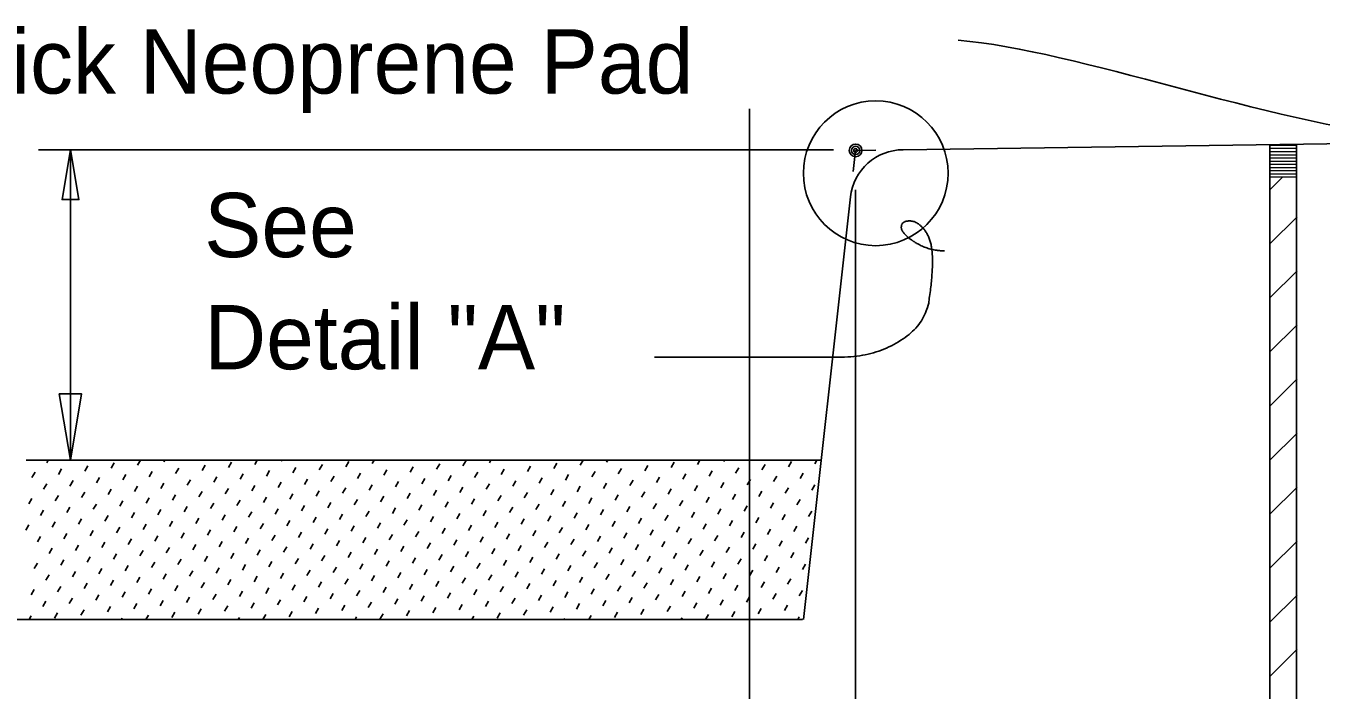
# Model space of a CAD drawing. Extents: x 21629.5 to 21698.8, y 56199.4 to 56237.6.
# Drawn here: x 21656.357 to 21660.425, y 56226.147 to 56228.232 of the extents above; entities that cross this region are included whole.
import ezdxf

# ---------------------------------------------------------------- set-up
doc = ezdxf.new("R2010")
doc.units = 0
for name, color, linetype in [('Dimension', 7, 'Continuous'), ('ExistSuperStruct', 7, 'Continuous'), ('Miscellaneous', 7, 'Continuous'), ('TextStructures', 7, 'Continuous')]:
    doc.layers.add(name, color=color, linetype=linetype)

msp = doc.modelspace()

# ---------------------------------------------------------------- linework, layer by layer
at = {"layer": 'Dimension'}
for p, q in [((21658.6296, 56224.0819), (21658.6296, 56227.9716)), ((21658.8938, 56227.8432), (21656.3966, 56227.8432)), ((21656.4966, 56227.8432), (21656.4966, 56226.8686)), ((21658.9631, 56227.8412), (21658.9557, 56227.7748)), ((21658.9631, 56227.8412), (21659.0262, 56227.8421)), ((21658.963, 56223.3626), (21658.963, 56227.7178))]:
    msp.add_line(p, q, dxfattribs=at)
for points in [[(21656.4967, 56227.8432), (21656.4703, 56227.687), (21656.5232, 56227.687)], [(21656.4966, 56226.8686), (21656.5319, 56227.0768), (21656.4614, 56227.0768)]]:
    msp.add_lwpolyline(points, close=True, dxfattribs=at)
for centre, radius in [((21659.0261, 56227.7695), 0.2273), ((21658.9631, 56227.8412), 0.0199), ((21658.9631, 56227.8412), 0.0131), ((21658.9631, 56227.8412), 0.00592)]:
    msp.add_circle(centre, radius, dxfattribs=at)
for points, degree in [([(21659.2853, 56228.1872), (21659.6642, 56228.1541), (21660.2494, 56227.9294), (21660.7118, 56227.8802)], 3), ([(21658.3309, 56227.1921), (21658.8009, 56227.1921), (21659.0206, 56227.1921), (21659.1804, 56227.2921), (21659.2044, 56227.436), (21659.2044, 56227.5579), (21659.1584, 56227.6199), (21659.1065, 56227.6199), (21659.1065, 56227.5799), (21659.1924, 56227.5259), (21659.2423, 56227.5259)], 2)]:
    msp.add_open_spline(points, degree=degree, dxfattribs=at)
at = {"layer": 'ExistSuperStruct'}
for p, q in [((21659.1125, 56227.8432), (21662.7249, 56227.8927)), ((21660.2645, 56225.0569), (21660.2645, 56227.8585)), ((21660.3479, 56224.8118), (21660.3479, 56227.8597)), ((21658.9468, 56227.695), (21658.7995, 56226.3686)), ((21658.7963, 56226.3686), (21654.863, 56226.3686))]:
    msp.add_line(p, q, dxfattribs=at)
msp.add_arc((21659.1125, 56227.6766), 0.1667, 90, 173.6598, dxfattribs=at)
at = {"layer": 'Miscellaneous'}
for p, q in [((21660.2647, 56227.8567), (21660.3481, 56227.8578)), ((21660.2648, 56227.8467), (21660.3482, 56227.8478)), ((21660.2649, 56227.8367), (21660.3483, 56227.8378)), ((21660.2651, 56227.8267), (21660.3485, 56227.8278)), ((21660.2652, 56227.8167), (21660.3486, 56227.8178)), ((21660.2653, 56227.8067), (21660.3487, 56227.8078)), ((21660.2655, 56227.7967), (21660.3489, 56227.7978)), ((21660.2656, 56227.7867), (21660.349, 56227.7878)), ((21660.2657, 56227.7767), (21660.3491, 56227.7778)), ((21660.2659, 56227.7667), (21660.3493, 56227.7678)), ((21660.2645, 56227.7177), (21660.3047, 56227.7578)), ((21660.266, 56227.7567), (21660.3494, 56227.7578)), ((21660.2645, 56227.548), (21660.3494, 56227.6329)), ((21660.2645, 56227.3783), (21660.3494, 56227.4632)), ((21660.2645, 56227.2085), (21660.3494, 56227.2935)), ((21660.2645, 56227.0388), (21660.3494, 56227.1237)), ((21660.2645, 56226.8691), (21660.3494, 56226.954)), ((21658.855, 56226.8686), (21656.3573, 56226.8686)), ((21656.3758, 56226.8147), (21656.3855, 56226.8314)), ((21656.4221, 56226.861), (21656.4265, 56226.8686)), ((21656.4587, 56226.8244), (21656.4685, 56226.8412)), ((21656.5417, 56226.8341), (21656.5514, 56226.8509)), ((21656.6246, 56226.8438), (21656.6343, 56226.8606)), ((21656.7075, 56226.8535), (21656.7163, 56226.8686)), ((21656.7442, 56226.8169), (21656.7539, 56226.8337)), ((21656.7905, 56226.8633), (21656.7936, 56226.8686)), ((21656.8271, 56226.8267), (21656.8368, 56226.8435)), ((21656.91, 56226.8364), (21656.9197, 56226.8532)), ((21656.993, 56226.8461), (21657.0027, 56226.8629)), ((21657.0759, 56226.8558), (21657.0833, 56226.8686)), ((21657.1125, 56226.8192), (21657.1222, 56226.836)), ((21657.1588, 56226.8655), (21657.1606, 56226.8686)), ((21657.1954, 56226.8289), (21657.2052, 56226.8457)), ((21657.2784, 56226.8387), (21657.2881, 56226.8555)), ((21657.3613, 56226.8484), (21657.371, 56226.8652)), ((21657.4443, 56226.8581), (21657.4503, 56226.8686)), ((21657.4809, 56226.8215), (21657.4906, 56226.8383)), ((21657.5272, 56226.8678), (21657.5276, 56226.8686)), ((21657.5638, 56226.8312), (21657.5735, 56226.848)), ((21657.6467, 56226.8409), (21657.6565, 56226.8577)), ((21657.7297, 56226.8507), (21657.7394, 56226.8675)), ((21657.7663, 56226.8141), (21657.776, 56226.8309)), ((21657.8126, 56226.8604), (21657.8174, 56226.8686)), ((21657.8492, 56226.8238), (21657.8589, 56226.8406)), ((21657.9322, 56226.8335), (21657.9419, 56226.8503)), ((21658.0151, 56226.8432), (21658.0248, 56226.86)), ((21658.098, 56226.853), (21658.1071, 56226.8686)), ((21658.1346, 56226.8163), (21658.1444, 56226.8331)), ((21658.181, 56226.8627), (21658.1844, 56226.8686)), ((21658.2176, 56226.8261), (21658.2273, 56226.8429)), ((21658.3005, 56226.8358), (21658.3102, 56226.8526)), ((21658.3835, 56226.8455), (21658.3932, 56226.8623)), ((21658.4664, 56226.8552), (21658.4741, 56226.8686)), ((21658.503, 56226.8186), (21658.5127, 56226.8354)), ((21658.5493, 56226.865), (21658.5514, 56226.8686)), ((21658.5859, 56226.8284), (21658.5957, 56226.8451)), ((21658.6689, 56226.8381), (21658.6786, 56226.8549)), ((21658.7518, 56226.8478), (21658.7615, 56226.8646)), ((21658.8348, 56226.8575), (21658.8412, 56226.8686)), ((21656.4124, 56226.778), (21656.4221, 56226.7948)), ((21656.4953, 56226.7878), (21656.5051, 56226.8046)), ((21656.5783, 56226.7975), (21656.588, 56226.8143)), ((21656.6612, 56226.8072), (21656.6709, 56226.824)), ((21656.7808, 56226.7803), (21656.7905, 56226.7971)), ((21656.8637, 56226.7901), (21656.8734, 56226.8068)), ((21656.9466, 56226.7998), (21656.9564, 56226.8166)), ((21657.0296, 56226.8095), (21657.0393, 56226.8263)), ((21657.1491, 56226.7826), (21657.1588, 56226.7994)), ((21657.2321, 56226.7923), (21657.2418, 56226.8091)), ((21657.315, 56226.8021), (21657.3247, 56226.8189)), ((21657.3979, 56226.8118), (21657.4077, 56226.8286)), ((21657.4345, 56226.7752), (21657.4443, 56226.792)), ((21657.5175, 56226.7849), (21657.5272, 56226.8017)), ((21657.6004, 56226.7946), (21657.6101, 56226.8114)), ((21657.6834, 56226.8043), (21657.6931, 56226.8211)), ((21657.8029, 56226.7775), (21657.8126, 56226.7942)), ((21657.8858, 56226.7872), (21657.8956, 56226.804)), ((21657.9688, 56226.7969), (21657.9785, 56226.8137)), ((21658.0517, 56226.8066), (21658.0614, 56226.8234)), ((21658.1713, 56226.7797), (21658.181, 56226.7965)), ((21658.2542, 56226.7895), (21658.2639, 56226.8063)), ((21658.3371, 56226.7992), (21658.3469, 56226.816)), ((21658.4201, 56226.8089), (21658.4298, 56226.8257)), ((21658.5396, 56226.782), (21658.5493, 56226.7988)), ((21658.6226, 56226.7917), (21658.6323, 56226.8085)), ((21658.7055, 56226.8015), (21658.7152, 56226.8183)), ((21658.7884, 56226.8112), (21658.7981, 56226.828)), ((21658.825, 56226.7746), (21658.8348, 56226.7914)), ((21656.449, 56226.7414), (21656.4587, 56226.7582)), ((21656.5319, 56226.7512), (21656.5417, 56226.768)), ((21656.6149, 56226.7609), (21656.6246, 56226.7777)), ((21656.6978, 56226.7706), (21656.7075, 56226.7874)), ((21656.7344, 56226.734), (21656.7442, 56226.7508)), ((21656.8174, 56226.7437), (21656.8271, 56226.7605)), ((21656.9003, 56226.7534), (21656.91, 56226.7702)), ((21656.9832, 56226.7632), (21656.993, 56226.78)), ((21657.0662, 56226.7729), (21657.0759, 56226.7897)), ((21657.1028, 56226.7363), (21657.1125, 56226.7531)), ((21657.1857, 56226.746), (21657.1954, 56226.7628)), ((21657.2687, 56226.7557), (21657.2784, 56226.7725)), ((21657.3516, 56226.7654), (21657.3613, 56226.7822)), ((21657.4711, 56226.7386), (21657.4809, 56226.7554)), ((21657.5541, 56226.7483), (21657.5638, 56226.7651)), ((21657.637, 56226.758), (21657.6467, 56226.7748)), ((21657.72, 56226.7677), (21657.7297, 56226.7845)), ((21657.8395, 56226.7408), (21657.8492, 56226.7576)), ((21657.9224, 56226.7506), (21657.9322, 56226.7674)), ((21658.0054, 56226.7603), (21658.0151, 56226.7771)), ((21658.0883, 56226.77), (21658.098, 56226.7868)), ((21658.1249, 56226.7334), (21658.1346, 56226.7502)), ((21658.2079, 56226.7431), (21658.2176, 56226.7599)), ((21658.2908, 56226.7529), (21658.3005, 56226.7696)), ((21658.3737, 56226.7626), (21658.3835, 56226.7794)), ((21658.4567, 56226.7723), (21658.4664, 56226.7891)), ((21658.4933, 56226.7357), (21658.503, 56226.7525)), ((21658.5762, 56226.7454), (21658.5859, 56226.7622)), ((21658.6592, 56226.7551), (21658.6689, 56226.7719)), ((21658.7421, 56226.7649), (21658.7518, 56226.7817)), ((21660.2645, 56226.6994), (21660.3494, 56226.7843)), ((21656.3661, 56226.7317), (21656.3758, 56226.7485)), ((21656.4027, 56226.6951), (21656.4124, 56226.7119)), ((21656.4856, 56226.7048), (21656.4953, 56226.7216)), ((21656.5686, 56226.7146), (21656.5783, 56226.7313)), ((21656.6515, 56226.7243), (21656.6612, 56226.7411)), ((21656.771, 56226.6974), (21656.7808, 56226.7142)), ((21656.854, 56226.7071), (21656.8637, 56226.7239)), ((21656.9369, 56226.7168), (21656.9466, 56226.7336)), ((21657.0198, 56226.7266), (21657.0296, 56226.7434)), ((21657.1394, 56226.6997), (21657.1491, 56226.7165)), ((21657.2223, 56226.7094), (21657.2321, 56226.7262)), ((21657.3053, 56226.7191), (21657.315, 56226.7359)), ((21657.3882, 56226.7288), (21657.3979, 56226.7456)), ((21657.4248, 56226.6922), (21657.4345, 56226.709)), ((21657.5078, 56226.702), (21657.5175, 56226.7188)), ((21657.5907, 56226.7117), (21657.6004, 56226.7285)), ((21657.6736, 56226.7214), (21657.6834, 56226.7382)), ((21657.7566, 56226.7311), (21657.7663, 56226.7479)), ((21657.7932, 56226.6945), (21657.8029, 56226.7113)), ((21657.8761, 56226.7042), (21657.8858, 56226.721)), ((21657.959, 56226.714), (21657.9688, 56226.7308)), ((21658.042, 56226.7237), (21658.0517, 56226.7405)), ((21658.1615, 56226.6968), (21658.1713, 56226.7136)), ((21658.2445, 56226.7065), (21658.2542, 56226.7233)), ((21658.3274, 56226.7162), (21658.3371, 56226.733)), ((21658.4103, 56226.726), (21658.4201, 56226.7428)), ((21658.5299, 56226.6991), (21658.5396, 56226.7159)), ((21658.6128, 56226.7088), (21658.6226, 56226.7256)), ((21658.6958, 56226.7185), (21658.7055, 56226.7353)), ((21658.7787, 56226.7283), (21658.7884, 56226.745)), ((21656.4393, 56226.6585), (21656.449, 56226.6753)), ((21656.5222, 56226.6682), (21656.5319, 56226.685)), ((21656.6052, 56226.6779), (21656.6149, 56226.6947)), ((21656.6881, 56226.6877), (21656.6978, 56226.7045)), ((21656.8076, 56226.6608), (21656.8174, 56226.6776)), ((21656.8906, 56226.6705), (21656.9003, 56226.6873)), ((21656.9735, 56226.6802), (21656.9832, 56226.697)), ((21657.0565, 56226.69), (21657.0662, 56226.7067)), ((21657.0931, 56226.6533), (21657.1028, 56226.6701)), ((21657.176, 56226.6631), (21657.1857, 56226.6799)), ((21657.2589, 56226.6728), (21657.2687, 56226.6896)), ((21657.3419, 56226.6825), (21657.3516, 56226.6993)), ((21657.4614, 56226.6556), (21657.4711, 56226.6724)), ((21657.5444, 56226.6653), (21657.5541, 56226.6821)), ((21657.6273, 56226.6751), (21657.637, 56226.6919)), ((21657.7102, 56226.6848), (21657.72, 56226.7016)), ((21657.8298, 56226.6579), (21657.8395, 56226.6747)), ((21657.9127, 56226.6676), (21657.9224, 56226.6844)), ((21657.9957, 56226.6774), (21658.0054, 56226.6941)), ((21658.0786, 56226.6871), (21658.0883, 56226.7039)), ((21658.1981, 56226.6602), (21658.2079, 56226.677)), ((21658.2811, 56226.6699), (21658.2908, 56226.6867)), ((21658.364, 56226.6796), (21658.3737, 56226.6964)), ((21658.447, 56226.6894), (21658.4567, 56226.7062)), ((21658.4836, 56226.6528), (21658.4933, 56226.6695)), ((21658.5665, 56226.6625), (21658.5762, 56226.6793)), ((21658.6494, 56226.6722), (21658.6592, 56226.689)), ((21658.7324, 56226.6819), (21658.7421, 56226.6987)), ((21658.8153, 56226.6916), (21658.825, 56226.7084)), ((21656.3563, 56226.6488), (21656.3661, 56226.6656)), ((21656.393, 56226.6122), (21656.4027, 56226.629)), ((21656.4759, 56226.6219), (21656.4856, 56226.6387)), ((21656.5588, 56226.6316), (21656.5686, 56226.6484)), ((21656.6418, 56226.6413), (21656.6515, 56226.6581)), ((21656.7247, 56226.6511), (21656.7344, 56226.6679)), ((21656.7613, 56226.6145), (21656.771, 56226.6312)), ((21656.8443, 56226.6242), (21656.854, 56226.641)), ((21656.9272, 56226.6339), (21656.9369, 56226.6507)), ((21657.0101, 56226.6436), (21657.0198, 56226.6604)), ((21657.1297, 56226.6167), (21657.1394, 56226.6335)), ((21657.2126, 56226.6265), (21657.2223, 56226.6433)), ((21657.2955, 56226.6362), (21657.3053, 56226.653)), ((21657.3785, 56226.6459), (21657.3882, 56226.6627)), ((21657.498, 56226.619), (21657.5078, 56226.6358)), ((21657.581, 56226.6287), (21657.5907, 56226.6455)), ((21657.6639, 56226.6385), (21657.6736, 56226.6553)), ((21657.7468, 56226.6482), (21657.7566, 56226.665)), ((21657.7835, 56226.6116), (21657.7932, 56226.6284)), ((21657.8664, 56226.6213), (21657.8761, 56226.6381)), ((21657.9493, 56226.631), (21657.959, 56226.6478)), ((21658.0323, 56226.6407), (21658.042, 56226.6575)), ((21658.1152, 56226.6505), (21658.1249, 56226.6673)), ((21658.1518, 56226.6139), (21658.1615, 56226.6307)), ((21658.2347, 56226.6236), (21658.2445, 56226.6404)), ((21658.3177, 56226.6333), (21658.3274, 56226.6501)), ((21658.4006, 56226.643), (21658.4103, 56226.6598)), ((21658.5202, 56226.6161), (21658.5299, 56226.6329)), ((21658.6031, 56226.6259), (21658.6128, 56226.6427)), ((21658.686, 56226.6356), (21658.6958, 56226.6524)), ((21658.769, 56226.6453), (21658.7787, 56226.6621)), ((21656.4296, 56226.5756), (21656.4393, 56226.5924)), ((21656.5125, 56226.5853), (21656.5222, 56226.6021)), ((21656.5954, 56226.595), (21656.6052, 56226.6118)), ((21656.6784, 56226.6047), (21656.6881, 56226.6215)), ((21656.7979, 56226.5778), (21656.8076, 56226.5946)), ((21656.8809, 56226.5876), (21656.8906, 56226.6044)), ((21656.9638, 56226.5973), (21656.9735, 56226.6141)), ((21657.0467, 56226.607), (21657.0565, 56226.6238)), ((21657.0833, 56226.5704), (21657.0931, 56226.5872)), ((21657.1663, 56226.5801), (21657.176, 56226.5969)), ((21657.2492, 56226.5899), (21657.2589, 56226.6066)), ((21657.3322, 56226.5996), (21657.3419, 56226.6164)), ((21657.4151, 56226.6093), (21657.4248, 56226.6261)), ((21657.4517, 56226.5727), (21657.4614, 56226.5895)), ((21657.5346, 56226.5824), (21657.5444, 56226.5992)), ((21657.6176, 56226.5921), (21657.6273, 56226.6089)), ((21657.7005, 56226.6019), (21657.7102, 56226.6187)), ((21657.8201, 56226.575), (21657.8298, 56226.5918)), ((21657.903, 56226.5847), (21657.9127, 56226.6015)), ((21657.9859, 56226.5944), (21657.9957, 56226.6112)), ((21658.0689, 56226.6041), (21658.0786, 56226.6209)), ((21658.1884, 56226.5773), (21658.1981, 56226.594)), ((21658.2714, 56226.587), (21658.2811, 56226.6038)), ((21658.3543, 56226.5967), (21658.364, 56226.6135)), ((21658.4372, 56226.6064), (21658.447, 56226.6232)), ((21658.5568, 56226.5795), (21658.5665, 56226.5963)), ((21658.6397, 56226.5893), (21658.6494, 56226.6061)), ((21658.7227, 56226.599), (21658.7324, 56226.6158)), ((21658.8056, 56226.6087), (21658.8153, 56226.6255)), ((21660.2645, 56226.5297), (21660.3494, 56226.6146)), ((21656.3832, 56226.5292), (21656.393, 56226.546)), ((21656.4662, 56226.539), (21656.4759, 56226.5557)), ((21656.5491, 56226.5487), (21656.5588, 56226.5655)), ((21656.632, 56226.5584), (21656.6418, 56226.5752)), ((21656.715, 56226.5681), (21656.7247, 56226.5849)), ((21656.7516, 56226.5315), (21656.7613, 56226.5483)), ((21656.8345, 56226.5412), (21656.8443, 56226.558)), ((21656.9175, 56226.551), (21656.9272, 56226.5678)), ((21657.0004, 56226.5607), (21657.0101, 56226.5775)), ((21657.1199, 56226.5338), (21657.1297, 56226.5506)), ((21657.2029, 56226.5435), (21657.2126, 56226.5603)), ((21657.2858, 56226.5532), (21657.2955, 56226.57)), ((21657.3688, 56226.563), (21657.3785, 56226.5798)), ((21657.4883, 56226.5361), (21657.498, 56226.5529)), ((21657.5712, 56226.5458), (21657.581, 56226.5626)), ((21657.6542, 56226.5555), (21657.6639, 56226.5723)), ((21657.7371, 56226.5652), (21657.7468, 56226.582)), ((21657.8567, 56226.5384), (21657.8664, 56226.5552)), ((21657.9396, 56226.5481), (21657.9493, 56226.5649)), ((21658.0225, 56226.5578), (21658.0323, 56226.5746)), ((21658.1055, 56226.5675), (21658.1152, 56226.5843)), ((21658.1421, 56226.5309), (21658.1518, 56226.5477)), ((21658.225, 56226.5406), (21658.2347, 56226.5574)), ((21658.308, 56226.5504), (21658.3177, 56226.5672)), ((21658.3909, 56226.5601), (21658.4006, 56226.5769)), ((21658.4738, 56226.5698), (21658.4836, 56226.5866)), ((21658.5104, 56226.5332), (21658.5202, 56226.55)), ((21658.5934, 56226.5429), (21658.6031, 56226.5597)), ((21658.6763, 56226.5527), (21658.686, 56226.5694)), ((21658.7593, 56226.5624), (21658.769, 56226.5792)), ((21656.4198, 56226.4926), (21656.4296, 56226.5094)), ((21656.5028, 56226.5023), (21656.5125, 56226.5191)), ((21656.5857, 56226.5121), (21656.5954, 56226.5289)), ((21656.6687, 56226.5218), (21656.6784, 56226.5386)), ((21656.7882, 56226.4949), (21656.7979, 56226.5117)), ((21656.8711, 56226.5046), (21656.8809, 56226.5214)), ((21656.9541, 56226.5144), (21656.9638, 56226.5311)), ((21657.037, 56226.5241), (21657.0467, 56226.5409)), ((21657.1566, 56226.4972), (21657.1663, 56226.514)), ((21657.2395, 56226.5069), (21657.2492, 56226.5237)), ((21657.3224, 56226.5166), (21657.3322, 56226.5334)), ((21657.4054, 56226.5264), (21657.4151, 56226.5432)), ((21657.442, 56226.4898), (21657.4517, 56226.5065)), ((21657.5249, 56226.4995), (21657.5346, 56226.5163)), ((21657.6079, 56226.5092), (21657.6176, 56226.526)), ((21657.6908, 56226.5189), (21657.7005, 56226.5357)), ((21657.7737, 56226.5286), (21657.7835, 56226.5454)), ((21657.8103, 56226.492), (21657.8201, 56226.5088)), ((21657.8933, 56226.5018), (21657.903, 56226.5186)), ((21657.9762, 56226.5115), (21657.9859, 56226.5283)), ((21658.0591, 56226.5212), (21658.0689, 56226.538)), ((21658.1787, 56226.4943), (21658.1884, 56226.5111)), ((21658.2616, 56226.504), (21658.2714, 56226.5208)), ((21658.3446, 56226.5138), (21658.3543, 56226.5306)), ((21658.4275, 56226.5235), (21658.4372, 56226.5403)), ((21658.5471, 56226.4966), (21658.5568, 56226.5134)), ((21658.63, 56226.5063), (21658.6397, 56226.5231)), ((21658.7129, 56226.516), (21658.7227, 56226.5328)), ((21658.7959, 56226.5258), (21658.8056, 56226.5426)), ((21656.4564, 56226.456), (21656.4662, 56226.4728)), ((21656.5394, 56226.4657), (21656.5491, 56226.4825)), ((21656.6223, 56226.4755), (21656.632, 56226.4923)), ((21656.7053, 56226.4852), (21656.715, 56226.502)), ((21656.7419, 56226.4486), (21656.7516, 56226.4654)), ((21656.8248, 56226.4583), (21656.8345, 56226.4751)), ((21656.9077, 56226.468), (21656.9175, 56226.4848)), ((21656.9907, 56226.4777), (21657.0004, 56226.4945)), ((21657.0736, 56226.4875), (21657.0833, 56226.5043)), ((21657.1102, 56226.4509), (21657.1199, 56226.4677)), ((21657.1932, 56226.4606), (21657.2029, 56226.4774)), ((21657.2761, 56226.4703), (21657.2858, 56226.4871)), ((21657.359, 56226.48), (21657.3688, 56226.4968)), ((21657.4786, 56226.4531), (21657.4883, 56226.4699)), ((21657.5615, 56226.4629), (21657.5712, 56226.4797)), ((21657.6445, 56226.4726), (21657.6542, 56226.4894)), ((21657.7274, 56226.4823), (21657.7371, 56226.4991)), ((21657.8469, 56226.4554), (21657.8567, 56226.4722)), ((21657.9299, 56226.4651), (21657.9396, 56226.4819)), ((21658.0128, 56226.4749), (21658.0225, 56226.4917)), ((21658.0958, 56226.4846), (21658.1055, 56226.5014)), ((21658.1324, 56226.448), (21658.1421, 56226.4648)), ((21658.2153, 56226.4577), (21658.225, 56226.4745)), ((21658.2982, 56226.4674), (21658.308, 56226.4842)), ((21658.3812, 56226.4772), (21658.3909, 56226.4939)), ((21658.4641, 56226.4869), (21658.4738, 56226.5037)), ((21658.5007, 56226.4503), (21658.5104, 56226.4671)), ((21658.5837, 56226.46), (21658.5934, 56226.4768)), ((21658.6666, 56226.4697), (21658.6763, 56226.4865)), ((21658.7495, 56226.4794), (21658.7593, 56226.4962)), ((21656.3735, 56226.4463), (21656.3832, 56226.4631)), ((21656.4101, 56226.4097), (21656.4198, 56226.4265)), ((21656.4931, 56226.4194), (21656.5028, 56226.4362)), ((21656.576, 56226.4291), (21656.5857, 56226.4459)), ((21656.6589, 56226.4389), (21656.6687, 56226.4556)), ((21656.7785, 56226.412), (21656.7882, 56226.4288)), ((21656.8614, 56226.4217), (21656.8711, 56226.4385)), ((21656.9444, 56226.4314), (21656.9541, 56226.4482)), ((21657.0273, 56226.4411), (21657.037, 56226.4579)), ((21657.1468, 56226.4143), (21657.1566, 56226.431)), ((21657.2298, 56226.424), (21657.2395, 56226.4408)), ((21657.3127, 56226.4337), (21657.3224, 56226.4505)), ((21657.3956, 56226.4434), (21657.4054, 56226.4602)), ((21657.5152, 56226.4165), (21657.5249, 56226.4333)), ((21657.5981, 56226.4263), (21657.6079, 56226.4431)), ((21657.6811, 56226.436), (21657.6908, 56226.4528)), ((21657.764, 56226.4457), (21657.7737, 56226.4625)), ((21657.8006, 56226.4091), (21657.8103, 56226.4259)), ((21657.8836, 56226.4188), (21657.8933, 56226.4356)), ((21657.9665, 56226.4285), (21657.9762, 56226.4453)), ((21658.0494, 56226.4383), (21658.0591, 56226.4551)), ((21658.169, 56226.4114), (21658.1787, 56226.4282)), ((21658.2519, 56226.4211), (21658.2616, 56226.4379)), ((21658.3348, 56226.4308), (21658.3446, 56226.4476)), ((21658.4178, 56226.4405), (21658.4275, 56226.4573)), ((21658.5373, 56226.4137), (21658.5471, 56226.4305)), ((21658.6203, 56226.4234), (21658.63, 56226.4402)), ((21658.7032, 56226.4331), (21658.7129, 56226.4499)), ((21658.7861, 56226.4428), (21658.7959, 56226.4596)), ((21660.2645, 56226.36), (21660.3494, 56226.4449)), ((21656.4467, 56226.3731), (21656.4564, 56226.3899)), ((21656.5297, 56226.3828), (21656.5394, 56226.3996)), ((21656.6126, 56226.3925), (21656.6223, 56226.4093)), ((21656.6955, 56226.4022), (21656.7053, 56226.419)), ((21656.8151, 56226.3754), (21656.8248, 56226.3922)), ((21656.898, 56226.3851), (21656.9077, 56226.4019)), ((21656.981, 56226.3948), (21656.9907, 56226.4116)), ((21657.0639, 56226.4045), (21657.0736, 56226.4213)), ((21657.1009, 56226.3686), (21657.1102, 56226.3847)), ((21657.1834, 56226.3776), (21657.1932, 56226.3944)), ((21657.2664, 56226.3874), (21657.2761, 56226.4042)), ((21657.3493, 56226.3971), (21657.359, 56226.4139)), ((21657.4323, 56226.4068), (21657.442, 56226.4236)), ((21657.4689, 56226.3702), (21657.4786, 56226.387)), ((21657.5518, 56226.3799), (21657.5615, 56226.3967)), ((21657.6347, 56226.3897), (21657.6445, 56226.4064)), ((21657.7177, 56226.3994), (21657.7274, 56226.4162)), ((21657.8372, 56226.3725), (21657.8469, 56226.3893)), ((21657.9202, 56226.3822), (21657.9299, 56226.399)), ((21658.0031, 56226.3919), (21658.0128, 56226.4087)), ((21658.086, 56226.4017), (21658.0958, 56226.4185)), ((21658.2056, 56226.3748), (21658.2153, 56226.3916)), ((21658.2885, 56226.3845), (21658.2982, 56226.4013)), ((21658.3715, 56226.3942), (21658.3812, 56226.411)), ((21658.4544, 56226.4039), (21658.4641, 56226.4207)), ((21658.4917, 56226.3686), (21658.5007, 56226.3841)), ((21658.5739, 56226.3771), (21658.5837, 56226.3938)), ((21658.6569, 56226.3868), (21658.6666, 56226.4036)), ((21658.7398, 56226.3965), (21658.7495, 56226.4133)), ((21656.3668, 56226.3686), (21656.3735, 56226.3801)), ((21656.6565, 56226.3686), (21656.6589, 56226.3727)), ((21656.7339, 56226.3686), (21656.7419, 56226.3824)), ((21657.0236, 56226.3686), (21657.0273, 56226.375)), ((21657.3906, 56226.3686), (21657.3956, 56226.3773)), ((21657.6803, 56226.3686), (21657.6811, 56226.3698)), ((21657.7577, 56226.3686), (21657.764, 56226.3796)), ((21658.0474, 56226.3686), (21658.0494, 56226.3721)), ((21658.1247, 56226.3686), (21658.1324, 56226.3818)), ((21658.4144, 56226.3686), (21658.4178, 56226.3744)), ((21658.7815, 56226.3686), (21658.7861, 56226.3767)), ((21660.2645, 56226.1903), (21660.3494, 56226.2752))]:
    msp.add_line(p, q, dxfattribs=at)

# ---------------------------------------------------------------- texts
at = {"layer": 'Dimension'}
msp.add_text('Thick Neoprene Pad', height=0.2016, dxfattribs=at).set_placement((21655.9955, 56228.0196))
at = {"layer": 'TextStructures'}
for s, p in [('See ', (21656.9167, 56227.5062)), ('Detail "A" ', (21656.9167, 56227.1542))]:
    msp.add_text(s, height=0.2016, dxfattribs=at).set_placement(p)

doc.saveas('drawing.dxf')
